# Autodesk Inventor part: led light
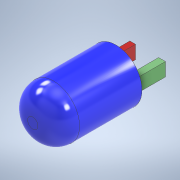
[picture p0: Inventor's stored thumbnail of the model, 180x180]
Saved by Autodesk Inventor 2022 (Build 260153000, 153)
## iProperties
Created: 2021-06
Part Number: led light
Material: Generic
Document SubType Name: Modeling
Designer: Dell
Density: 1 g/cm^3
Appearance: Default
Author: Dell
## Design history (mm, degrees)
sketch "Sketch1"
  geometry: C1 r 2.5 at (0, 0); 1 further point
  constraints: 1 centre point, 1 coincident
  dimensions: "d0" = 5 diameter of C1
extrude "Extrusion1" new body sketch "Sketch1" distance "d1" = 8; taper "d2" = 0 deg
fillet "Fillet1" dims "d3" = 2
sketch "Sketch2"
  geometry: L1 (1.668, 0.5)-(1.114, 0.5); L2 (1.114, 0.5)-(1.114, -0.783); L3 (1.114, -0.783)-(1.668, -0.783); L4 (1.668, -0.783)-(1.668, 0.5); L5 (-1.096, 0.5)-(-1.755, 0.5); L6 (-1.755, 0.5)-(-1.755, -0.783); L7 (-1.755, -0.783)-(-1.096, -0.783); L8 (-1.096, -0.783)-(-1.096, 0.5); 1 further point
  constraints: 16 end point, 4 parallel, 2 horizontal, 2 perpendicular, 2 point on line
extrude "Extrusion2" join sketch "Sketch2" distance "d4" = 3; taper "d5" = 0 deg
body "Solid1"
